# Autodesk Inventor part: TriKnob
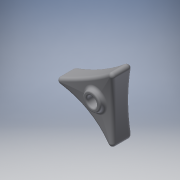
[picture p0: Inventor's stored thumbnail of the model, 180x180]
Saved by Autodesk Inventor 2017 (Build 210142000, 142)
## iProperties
Created: 2016-02
Part Number: TriKnob
Material: Generic
Document SubType Name: Modeling
Designer: Luke Denby
Density: 1 g/cm^3
Appearance: Default
Author: Luke Denby
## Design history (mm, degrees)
sketch "Sketch1"
  geometry: L1 (0, 0)-(0, -50); L2 (0, -50)-(43.301, -25); L3 (43.301, -25)-(0, 0); 1 further point
  constraints: 6 end point, 1 horizontal alignment, 1 midpoint, 1 vertical
  dimensions: "d0" = 50 distance of L1.start L1.end; "d1" = 50 distance of L1.end L2.end (= d0)
extrude "Extrusion1" new body sketch "Sketch1" distance "d2" = 15; taper "d3" = 0 deg
sketch "Sketch2"
  geometry: L1 (-19.63, 28)-(-14.434, 31); L2 (-14.434, 31)-(-9.238, 28); L3 (-9.238, 28)-(-9.238, 22); L4 (-9.238, 22)-(-14.434, 19); L5 (-14.434, 19)-(-19.63, 22); L6 (-19.63, 22)-(-19.63, 28); L7 (-43.301, 25)-(0, 25); L8 (0, 0)-(0, 50) reference; L9 (0, 0)-(-21.651, 37.5); L10 (0, 50)-(-43.301, 25) reference; L11 (0, 50)-(-21.651, 12.5); L12 (-43.301, 25)-(0, 0) reference; 1 further point
  constraints: 18 end point, 3 midpoint, 2 point on line, 1 vertical, 13 other
  dimensions: "d4" = 6 distance of L5.end L1.start
extrude "Extrusion2" cut sketch "Sketch2" distance "d5" = 9; taper "d6" = 0 deg
sketch "Sketch4"
  geometry: L1 (-9.238, -22)-(-14.434, -19) reference; L2 (-9.238, -28)-(-9.238, -22) reference; L3 (-14.434, -31)-(-9.238, -28) reference; L4 (-19.63, -28)-(-14.434, -31) reference; L5 (-19.63, -22)-(-19.63, -28) reference; L6 (-14.434, -19)-(-19.63, -22) reference; L7 (-14.434, -19)-(-14.434, -31); L8 (-9.238, -25)-(-19.63, -25); C1 r 3.15 at (-14.434, -25); 1 further point
  constraints: 4 end point, 3 midpoint, 1 centre point, 1 vertical
  dimensions: "d12" = 6.3 diameter of C1
extrude "Extrusion4" cut sketch "Sketch4" stored distance "d13" = 9; taper "d14" = 0 deg
sketch "Sketch5"
  geometry: L1 (0, 0)-(50, 0) reference; L2 (25, 0)-(25, 15) reference; L3 (28, 6)-(22, 6) reference; L4 (0, 0)-(50, 0); L5 (25, 0)-(0, 0) reference; A1 r 105.667 centre (25, -102.667) between (50, 0) and (0, 0); 1 further point
  constraints: 3 point on circle, 2 end point, 1 centre point, 1 collinear, 1 point on line
  dimensions: "d51" = 3 distance of L2.start point (25, 3)
extrude "Extrusion5" cut sketch "Sketch5" distance "d19" = 14.5; taper "d20" = 0 deg
pattern_circular "Circular Pattern3" dims angle "d25" = 360 deg
sketch "Sketch6"
  geometry: C1 r 6 at (-14.434, 25); 5 further points
  constraints: 2 coincident, 1 centre point, 5 other
  dimensions: "d31" = 12 diameter of C1
extrude "Extrusion6" join sketch "Sketch6" distance "d32" = 6; taper "d33" = 0 deg
sketch "Sketch7"
  geometry: L1 (0, 50)-(-43.301, 25); L2 (0, 50)-(-43.301, 25) reference; L3 (0, 0)-(-43.301, 25); L4 (0, 50)-(0, 0); L5 (0, 0)-(0, 50) reference; A1 r 111 centre (-75.725, -81.159) between (0, 0) and (-43.301, 25); A2 r 111 centre (-75.725, 131.159) between (-43.301, 25) and (0, 50); A3 r 111 centre (108.148, 25) between (0, 50) and (0, 0)
  constraints: 6 end point, 6 point on circle, 3 centre point, 2 collinear
  dimensions: "d40" = 111 radius of A3; "d41" = 111 radius of A1 (= d40); "d42" = 111 radius of A2 (= d41)
extrude "Extrusion7" cut sketch "Sketch7" stored distance "d43" = 3; taper "d44" = 0 deg
fillet "Fillet12" dims "d45" = 1
fillet "Fillet14" dims "d47" = 2
fillet "Fillet16" dims "d49" = 3
fillet "Fillet17" dims "d50" = 2
fillet "Fillet18" dims "d52" = 2
sketch "Sketch8"
  geometry: C1 r 3.3 at (0, 0); C2 r 5 at (0, 0) reference; 1 further point
  constraints: 1 centre point, 1 coincident
  dimensions: "d53" = 6.6 diameter of C1
extrude "Extrusion8" cut sketch "Sketch8" stored distance "d54" = 3; taper "d55" = 0 deg
fillet "Fillet19" dims "d56" = 1
sketch "Sketch9"
  geometry: C1 r 3.3 at (-14.434, 25) reference; C2 r 6.7 at (-14.434, 25); 1 further point
  constraints: 1 centre point, 1 coincident
  dimensions: "d57" = 13.4 diameter of C2
extrude "Extrusion9" cut sketch "Sketch9" distance "d58" = 4.5; taper "d59" = 0 deg
body "Solid1"
node "Projected Loop1"
